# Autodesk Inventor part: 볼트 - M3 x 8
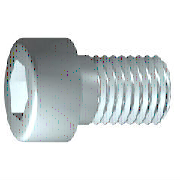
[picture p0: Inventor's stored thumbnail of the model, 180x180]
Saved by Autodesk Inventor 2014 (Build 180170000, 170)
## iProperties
IsCustomPart: 0
Created: 2012-02
Part Number: 볼트 - M3 x 8
Material: 스테인리스강
Description: 6각 소켓 머리 캡 나사
Document SubType Name: Modeling
Standard: ISO 4762
Designer: mduedu
Standard Revision: Fourth edition 2004-03-01
Standards Organization: ISO
Language: ko-KR
Size Designation: M3 x 8
Categories: <MemberInstance><Categories><Category DisplayName="조임쇠" InternalName="e4da775c-781d-43d5-af7c-5136215cf5a6" Mnemonic="FSTN"><Category DisplayName="볼트" InternalN
Density: 8.08 g/cm^3
Mass: 0.955869 g
Surface Area: 1.83001 cm^2
Volume: 0.118301 cm^3
Appearance: 반광택
Author: mduedu
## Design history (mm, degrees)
sketch "스케치1"
  geometry: L1 (-0.867, 0)-(8, 0); L2 (8, 0)-(8, 1.5); L3 (8, 1.5)-(1.25, 1.5); L4 (1.25, 1.5)-(0.943, 1.5); L5 (0.943, 1.5)-(0, 1.5); L6 (0, 1.5)-(0, 2.75); L7 (0, 2.75)-(-3, 2.75); L8 (-3, 2.75)-(-3, 1.443); L9 (-3, 1.443)-(-1.7, 1.443); L10 (-1.7, 1.443)-(-0.867, 0); L11 (-5.2, 0)-(10.2, 0) reference; L12 (0, -0.55)-(0, 3.3) reference; L13 (1.25, 1.5)-(0, 1.5)
  constraints: 22 end point, 6 parallel, 2 collinear, 2 perpendicular, 1 horizontal, 1 point on line
  dimensions: "d1" = 6.75 distance from line of L3.end L2 (= GEL); "d2" = 0.30683 distance of L4.end L3.end (computed from GAL); "d3" = 3 distance between parallel lines of L8 L6 (= KOH); "d4" = 1.3 distance of L8.end L9.end (= INTI); "d5" = 60 deg angle of L10 L1; "d6" = 3 diameter of L3 L1 (= GD); "d7" = 3 diameter of L5 L1 (= BDM); "d8" = 2.88675 diameter of L9 L1 (= 1.1547 x SW); "d9" = 5.5 diameter of L7 L1 (= KOD); "d26" = 8 distance between parallel lines of L12 L2 (= NLG)
revolve "본체" sketch "스케치1" stored, may be unused: angle "d10" = 90 deg
sketch "스케치2"
  geometry: L1 (0, -3.85)-(0, 3.85) reference; L2 (-3.85, 0)-(3.85, 0) reference; L3 (1.443, 0)-(0.722, -1.25); L4 (0.722, -1.25)-(-0.722, -1.25); L5 (-0.722, -1.25)-(-1.443, 0); L6 (-1.443, 0)-(-0.722, 1.25); L7 (-0.722, 1.25)-(0.722, 1.25); L8 (0.722, 1.25)-(1.443, 0); 2 further points
  constraints: 12 end point, 1 coincident, 1 horizontal alignment, 1 point on line, 12 other
extrude "슬롯" join sketch "스케치2" stored distance "d11" = 10; taper "d12" = 0 deg
workplane "Work Plane1"
fillet "Fillet2" dims "d30" = 0.1 (= R)
body "Solid1"
fillet "모깎기1" dims "d17" = 0.3 (= RR)
feature "스레드" dims "d13" = 6.75 (= GEL), "d14" = 0
chamfer "모따기1" distance "d15" = 0.30673 (= -0.5 x SPD + 0.5 x GD); stored, may be unused: second distance "d16" = 0.30673 (= GUL), angle "d27" = 45 deg
other parameters: "GD" = 3 [user parameter; used in 2 equation terms], "NLG" = 8 [user parameter; used in 1 equation term], "GEL" = 6.75 [user parameter; used in 2 equation terms], "KOD" = 5.5 [user parameter; used in 1 equation term], "KOH" = 3 [user parameter; used in 1 equation term], "INTI" = 1.3 [user parameter; used in 1 equation term], "GAL" = 0.30673 (= 0.61345 x PTC) [user parameter; used in 1 equation term], "GUL" = 0.30673 (= 0.61345 x PTC) [user parameter; used in 1 equation term], "BDM" = 3 (= NND) [user parameter; used in 1 equation term], "SW" = 2.5 [user parameter; used in 2 equation terms], "RR" = 0.3 [user parameter; used in 1 equation term], "SPD" = 2.38655 (= NND - 1.2269 x PTC) [user parameter; used in 1 equation term], "d19" = 0, "d28" = 0, "d29" = 0, "R" = 0.1 [user parameter; used in 1 equation term], "TOA" = 30 deg [user parameter], "GD1" = 2.38655 (= THREADDIA - 1.2269 x PTC) [user parameter], "THREADDIA" = 3 [user parameter; used in 1 equation term], "FAWI" = 45 deg [user parameter], "PTC" = 0.5 [user parameter; used in 5 equation terms], "NND" = 3 [user parameter; used in 2 equation terms], "E0" = 2.8875 (= 1.155 x SW) [user parameter]
